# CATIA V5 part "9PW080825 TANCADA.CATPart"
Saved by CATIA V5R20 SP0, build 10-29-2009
Part number: 9PW080825 TANCADA
Revision: ANY
Definition: UNKNOWN
Nomenclature: 9PW080825 TANCADA
Source: Unknown
Bounding box of the stored display mesh (mm): x -140 to 0, y -6.999 to 4.5, z -4.1 to 4.1
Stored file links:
  C:\Users\Utente\Desktop\IO LAVORO\3D X SITO CF\CUMSA\3D files PW\pw080825\pw080825_injection\9PW080825 TANCADA.CATPart
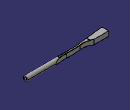
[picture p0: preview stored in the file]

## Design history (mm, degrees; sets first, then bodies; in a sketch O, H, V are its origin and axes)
Body1 "Chaflán2" (main body)
  Solid1: solid without history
